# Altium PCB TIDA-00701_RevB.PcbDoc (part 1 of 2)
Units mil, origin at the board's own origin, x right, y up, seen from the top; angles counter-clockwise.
Board outline 4724.41 x 3228.35 mil, 2 copper layers (Top Layer, Bottom Layer), stack 62 mil thick; 170 components, 75 nets, 385 pads, 92 vias.
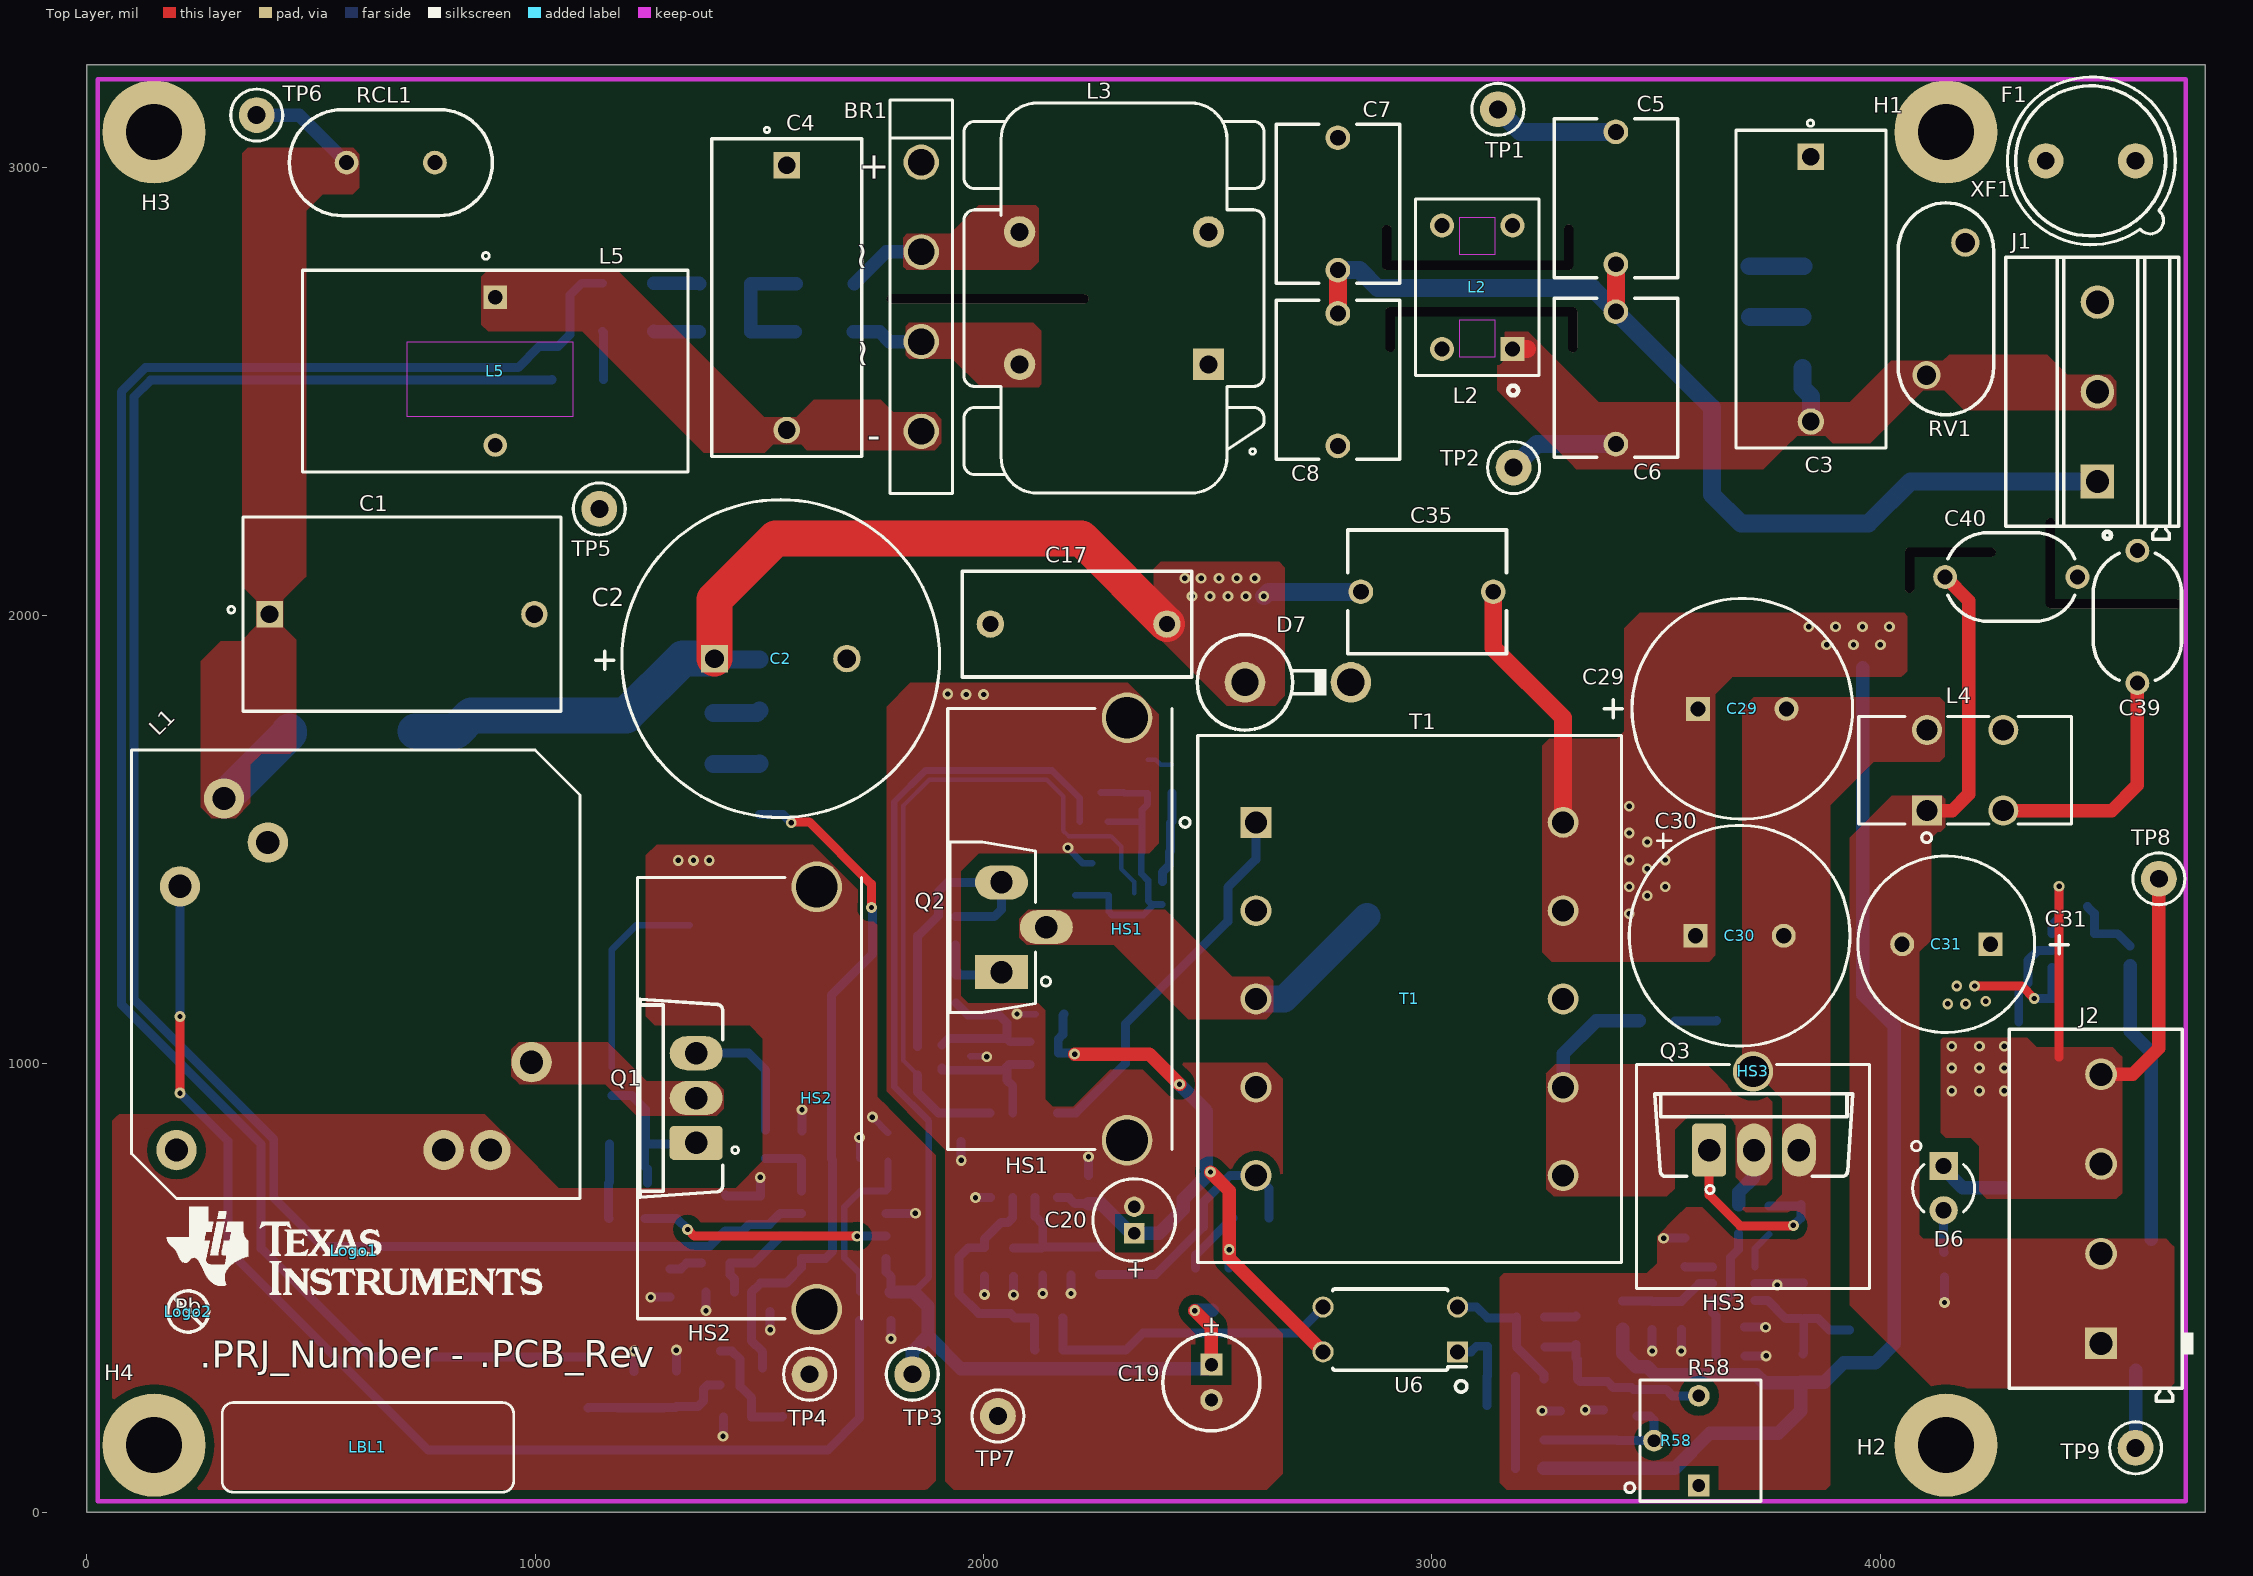
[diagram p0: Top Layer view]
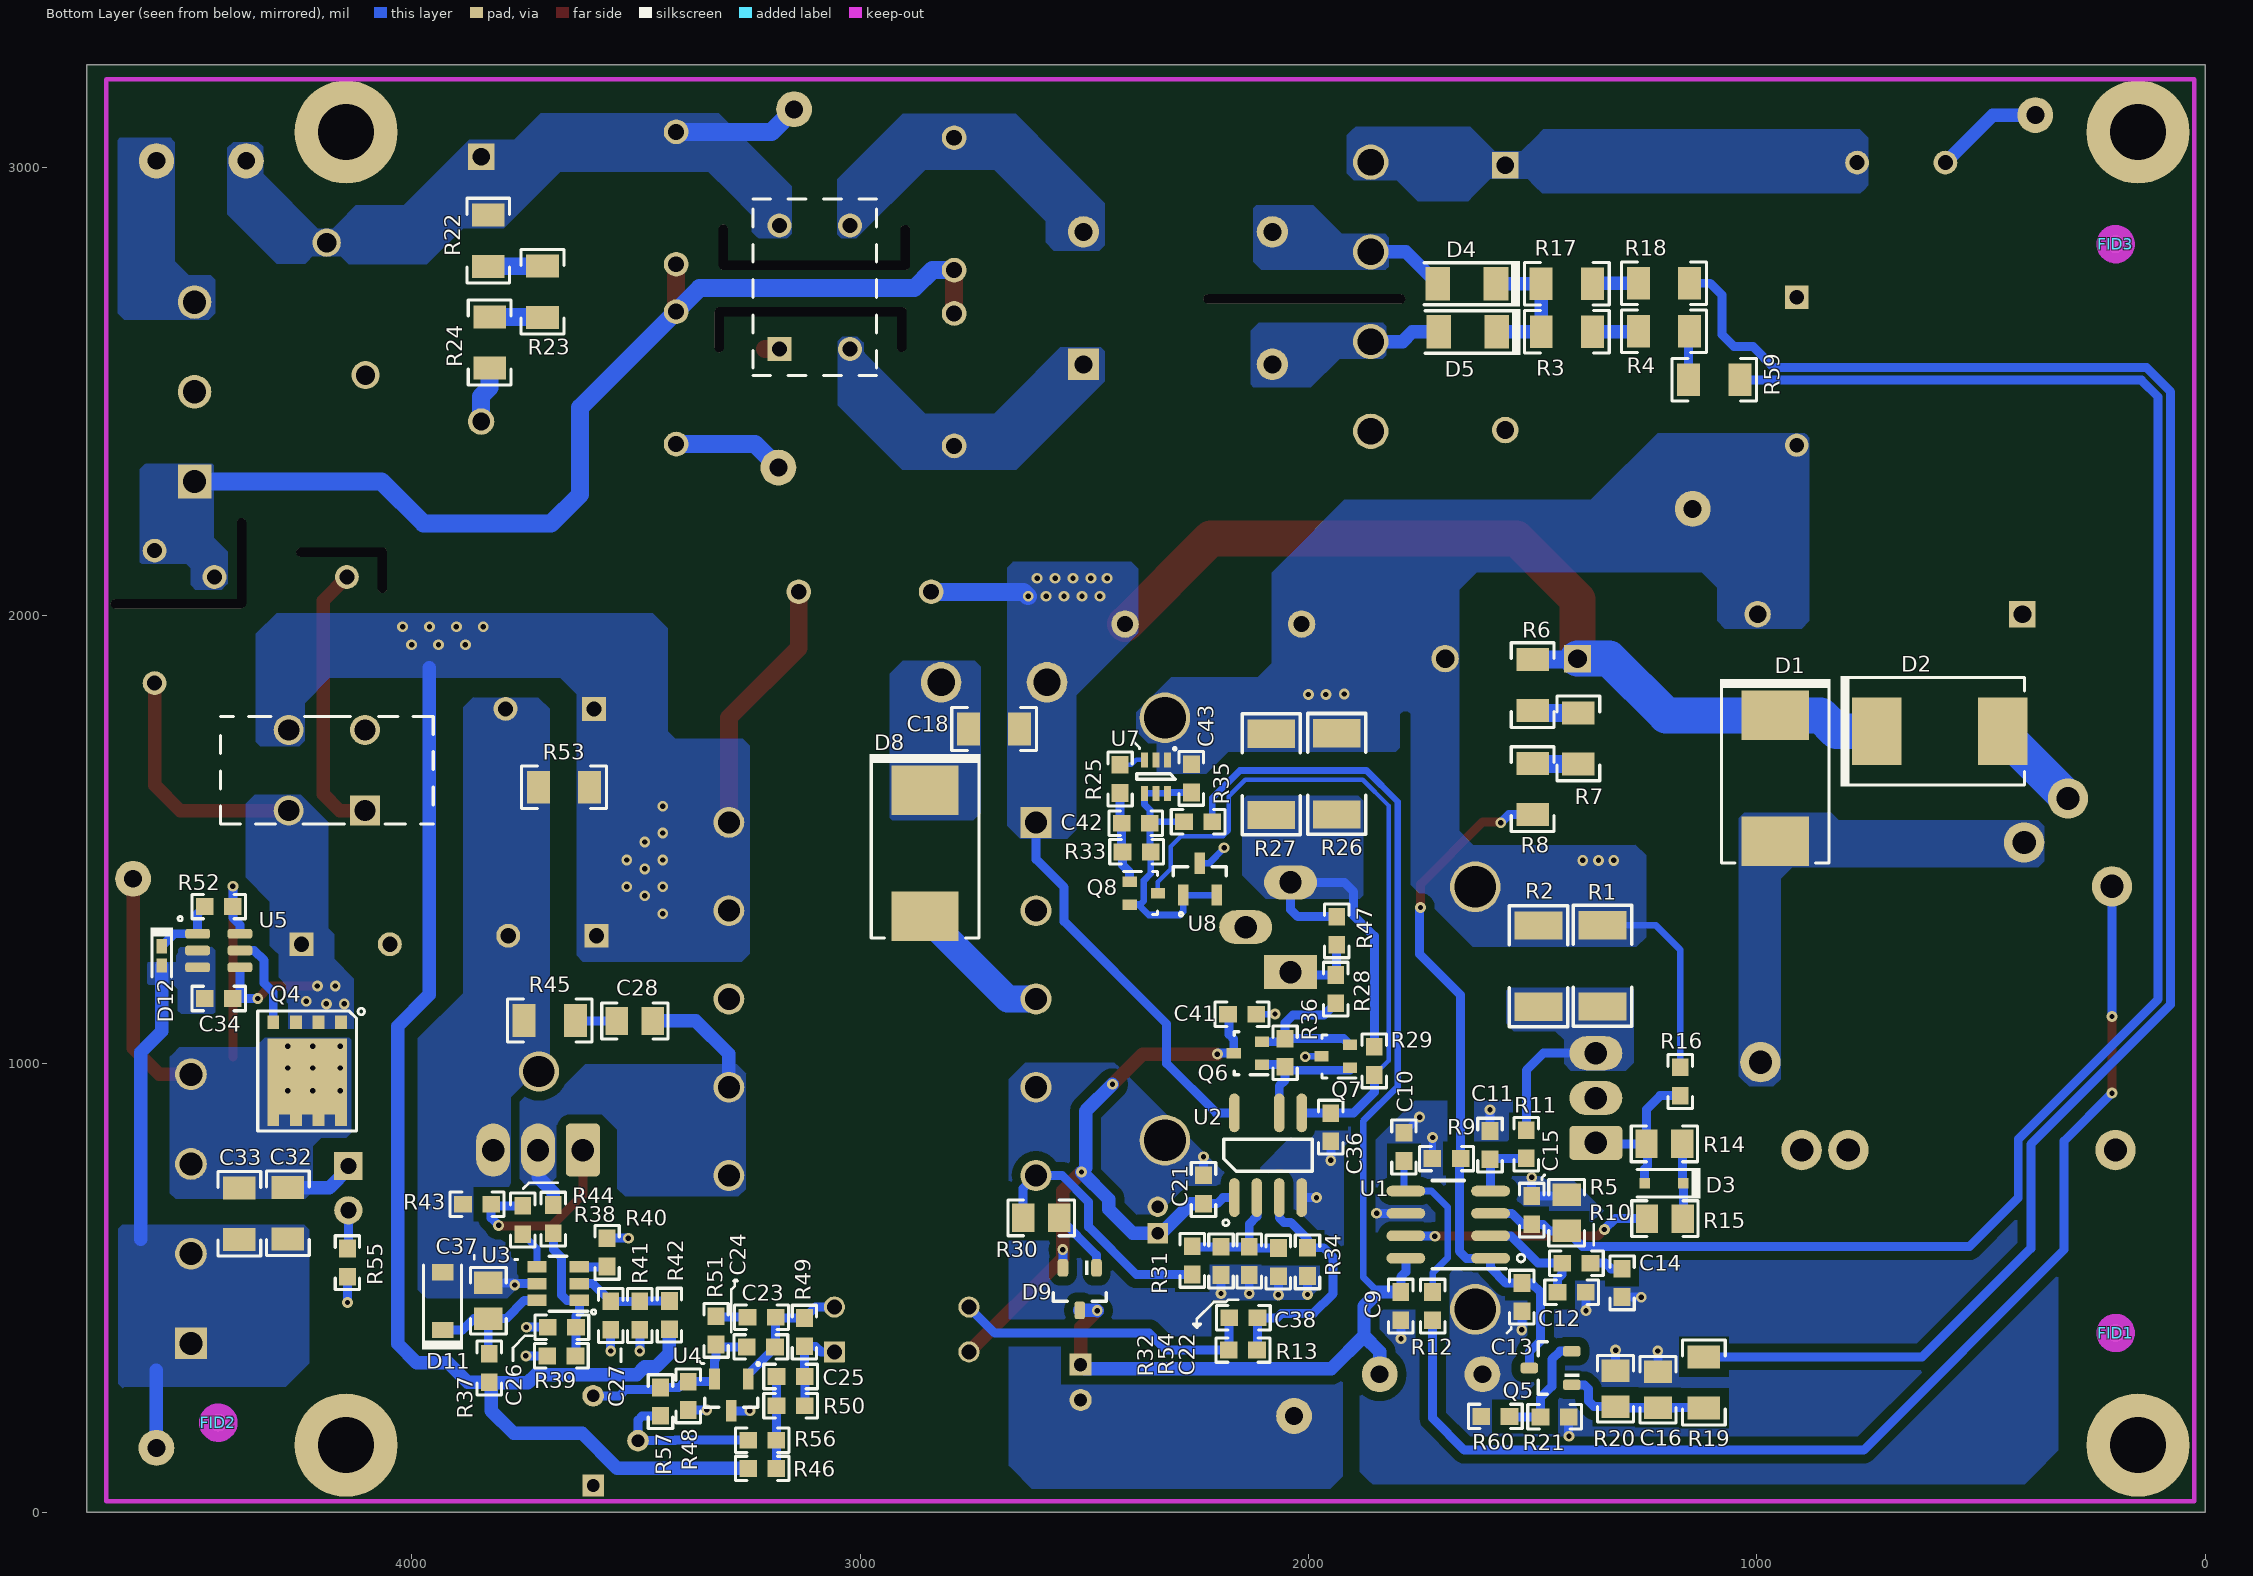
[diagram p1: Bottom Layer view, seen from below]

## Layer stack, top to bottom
Top Solder: solder mask 0.4, Solder Resist, Dk 3.5
Top Layer: signal copper 1.4
Dielectric1: core 59.2, FR-4, Dk 4.8
Bottom Layer: signal copper 1.4
Bottom Solder: solder mask 0.4, Solder Resist, Dk 3.5

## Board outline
0,0 0,3228.35 4724.41,3228.35 4724.41,0

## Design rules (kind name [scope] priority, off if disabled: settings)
AcuteAngle [All] p1: minimum=4.50000000000000E+0001 checktracksonly=FALSE
AssemblyTestPointUsage [All] p1: valid=2
Clearance Clearance_1 [IsSMTPin vs IsVia] p1: gap=8
Clearance Clearance_Poly [InPolygon] p2: gap=20
Clearance [All] p3: gap=8
ComponentClearance ComponentClearance_Shunt [InComponentClass('Header') vs InComponentClass('Shunt')] p1: gap=0 collisioncheckmode=3 verticalgap=0 showdistances=FALSE
ComponentClearance ComponentClearance_MountingHoles_FiducialMarks [InComponentClass('Mounting Holes') vs InComponentClass('FiducialMark')] p2: gap=20 collisioncheckmode=3 verticalgap=10 showdistances=FALSE
ComponentClearance ComponentClearance_Logo [InComponentClass('Logo')] p3: gap=0 collisioncheckmode=3 verticalgap=0 showdistances=FALSE
ComponentClearance ComponentClearance_ScrewToNut [(HasFootprint('NY PMS 440 0025 PH')) vs (HasFootprint('Keystone_1902C'))] p4: gap=5 collisioncheckmode=3 verticalgap=10 showdistances=FALSE
ComponentClearance ComponentClearance_MountingHoles [InComponentClass('Mounting Holes')] p5: gap=50 collisioncheckmode=3 verticalgap=100000 showdistances=FALSE
ComponentClearance ComponentClearance_SmallPassives [HasFootprint('0201*') or HasFootprint('0402*') or HasFootprint('0508') or HasFootprint('0603*') or HasFootprint('0612') or HasFootprint('0805*') or HasFootprint('0815*') or HasFootprint('0830*') or HasFootprint('1206*') or HasFootprint('1210*') or HasFootprint('1808*') or HasFootprint('1812*') or HasFootprint('1825*') or HasFootprint('2010*') or HasFootprint('2220*') or HasFootprint('2225*') or HasFootprint('2512*') or HasFootprint('2728*') or HasFootprint('3518*') vs HasFootprint('0201*') or HasFootprint('0402*') or HasFootprint('0508') or HasFootprint('0603*') or HasFootprint('0612') or HasFootprint('0805*') or HasFootprint('0815*') or HasFootprint('0830*') or HasFootprint('1206*') or HasFootprint('1210*') or HasFootprint('1808*') or HasFootprint('1812*') or HasFootprint('1825*') or HasFootprint('2010*') or HasFootprint('2220*') or HasFootprint('2225*') or HasFootprint('2512*') or HasFootprint('2728*') or HasFootprint('3518*')] p6: gap=10 collisioncheckmode=3 verticalgap=10 showdistances=FALSE
DiffPairsRouting [All] p1: maxlimit=100 minlimit=10 mostfreqgap=10 toplayer_minwidth=15 toplayer_maxwidth=15 toplayer_prefwidth=15 bottomlayer_minwidth=15 bottomlayer_maxwidth=15 bottomlayer_prefwidth=15 maxuncoupledlength=1000
FabricationTestPointUsage TestPointUsage [All] p1: valid=2 allowmultiple=FALSE
FabricationTestpoint Testpoint [All] p1: side=3 testpointundercomponent=TRUE minsize=40 maxsize=100 preferedsize=60 minholesize=0 maxholesize=40 preferedholesize=32 testpointgrid=1 allowsidetop=TRUE allowsidebottom=TRUE usegrid=TRUE gridtolerance=0.01
FanoutControl Fanout_LCC [IsLCC] p1: bgadir=Out bgaviamode=Centered fanoutstyle=Auto fanoutdirection=Alternating viagrid=1 // Fanout_LCC (Default Rule)
FanoutControl Fanout_BGA [IsBGA] p2: bgadir=Out bgaviamode=Centered fanoutstyle=Auto fanoutdirection=Alternating viagrid=1 // Fanout_BGA (Default Rule)
FanoutControl Fanout_Default [All] p4: bgadir=Out bgaviamode=Centered fanoutstyle=Auto fanoutdirection=Alternating viagrid=1 // Fanout_Default (Default Rule)
FanoutControl Fanout_Small [(CompPinCount < 5)] p5: bgadir=Out bgaviamode=Centered fanoutstyle=Auto fanoutdirection=OutThenIn viagrid=1 // Fanout_Small (Default Rule)
Height [All] p1: minheight=0 maxheight=2000 prefheight=100
HoleSize [All] p1: absolutevalues=TRUE maxlimit=251 minlimit=8 maxpercent=80.000 minpercent=20.000
MinimumAnnularRing MinimumAnnularRing_ThermalPadVias [IsVia and InAnyComponent] p1: minimumring=5.91
MinimumAnnularRing [All] p2: minimumring=9
MinimumSolderMaskSliver MinimumSolderMaskSliver_Logo [InComponentClass('Logo') vs InComponentClass('Logo')] p1: minsoldermaskwidth=0.7
MinimumSolderMaskSliver [All] p2: minsoldermaskwidth=3.94
PlaneConnect [All] p1: planeconnectstyle=Direct reliefexpansion=10 reliefentries=4 reliefconductorwidth=10 reliefairgap=10
PolygonConnect [All] p1: connectstyle=Direct reliefconductorwidth=10 reliefentries=4 polygonreliefangle="90 Angle" airgapwidth=10
RoutingVias ThermalPadVias [IsVia and InAnyComponent] p1: holewidth=7.87 width=19.68 viastyle="Through Hole" minholewidth=7.87 minwidth=19.68 maxholewidth=12.99 maxwidth=23.62
RoutingVias [All] p2: holewidth=12 width=24 viastyle="Through Hole" minholewidth=7.87 minwidth=24 maxholewidth=16 maxwidth=34
SilkToSilkClearance SilkToSilkClearance_Pb-FreeLogo [(HasFootprint('Pb-Free_Overlay_Medium') OR HasFootprint('Pb-Free_Overlay_Small')) vs (HasFootprint('Pb-Free_Overlay_Medium') OR HasFootprint('Pb-Free_Overlay_Small'))] p1: silktosilkclearance=0
SilkToSilkClearance [All] p2: silktosilkclearance=5
SilkToSolderMaskClearance SilkscreenOverComponentPads [IsPad] p1: minsilkscreentomaskgap=1 clearancetoexposedcopper=TRUE
SolderMaskExpansion [All] p1: expansion=2.5
UnpouredPolygon [All] p1: allowunpoured=FALSE
Width [All] p1: maxlimit=120 minlimit=6 preferedwidth=10 checkconnectedcopper=TRUE
14 further rules are at their usual default settings.

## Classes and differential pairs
net class HV_net: NetR6_2 NetR17_1
component class TIDA-00701_PFC: BR1 C1 C2 C3 C4 C5 C6 C7 C8 C9 C10 C11 C12 C13 C14 C15 C16 C42 C43 D1 D2 D3 D4 D5 F1 HS1 J1 L1 L2 L3 L5 Q1 Q5 Q8 R1 R2 R3 R4 R5 R6 R7 R8 R9 R10 R11 R12 R14 R15 R16 R17 R18 R19 R20 R21 R22 R23 R24 R25 R33 R35 R59 R60 RCL1 RV1 TP1 TP2 TP3 TP4 TP5 TP6 U1 U7 U8 XF1
component class TIDA-00701_Flyback: C17 C18 C19 C20 C21 C22 C23 C24 C25 C26 C27 C28 C29 C30 C31 C32 C33 C34 C35 C36 C37 C38 C39 C40 C41 D6 D7 D8 D9 D11 D12 HS2 HS3 J2 L4 Q2 Q3 Q4 Q6 Q7 R13 R26 R27 R28 R29 R30 R31 R32 R34 R36 R37 R38 R39 R40 R41 R42 R43 R44 R45 R46 R47 R48 R49 R50 R51 R52 R53 R54 R55 R56 R57 R58 T1 TP7 TP8 TP9 U2 U3 U4 U5 U6
component class Hardware_ANSI-B: !PCB1 FID1 FID2 FID3 H1 H2 H3 H4 LBL1 Logo1 Logo2 Logo3 ZZ1 ZZ2 ZZ3 ZZ4

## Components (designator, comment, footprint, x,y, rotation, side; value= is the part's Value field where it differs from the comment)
BR1 "GBU6J" GBU 1861,2711 r270 top
C1 "B32922C3684M" B32922_18.5mm 703,2003 r0 top
C2 "UCY2W820MHD6" CAPPRD750W80D1800H3150 1547.64,1904.05 r0 top
C3 "B32922C3334M" B32922_14.5mm 3845,2728 r270 top
C4 "B32922C3334M" B32922_14.5mm 1561,2709 r270 top
C5 "CS75ZU2GA152MYNKA" E_900x700x900 3410,2931 r270 top
C6 "CS75ZU2GA152MYNKA" E_900x700x900 3410,2530 r90 top
C7 "CS80ZU2GA222MYNKA" E_900x700x900 2790,2918 r270 top (schematic designator C43)
C8 "CS80ZU2GA222MYNKA" E_900x700x900 2790,2526 r90 top (schematic designator C39)
C9 "GRM188R61H105KAALD" 0603 1794,460 r270 bottom
C10 "GRM1885C1H180JA01D" 0603 1787,815 r90 bottom
C11 "C1608C0G1H102J" 0603 1595,819 r90 bottom
C12 "C1608X5R1C105K" 0603 1412.96,491.13 r180 bottom
C13 "C1608C0G1H102J" 0603 1524,480 r270 bottom
C14 "C1608X5R1E335K080AC" 0603 1300.5,511.76 r270 bottom
C15 "C1608C0G1H102J" 0603 1502,674 r90 bottom
C16 "C2012X5R1E106K125AB" 0805_HV 1220.22,273.72 r90 bottom
C17 "B32921C3104M" B32921_1300x1200x600 2212,1981 r180 top
C18 "C3216X7R2J222K" 1206 2701,1747 r0 bottom
C19 "35ZLJ47MTA5X11" ZLJ_500x1100 2508,290 r270 top
C20 "UVR1H100MDD6TP" FC_400x1100 2336,652 r90 top
C21 "C1608X7R1H104K" 0603 2234,720 r90 bottom
C22 "06035A4R7CAT2A" 0603 2067,558 r270 bottom
C23 "C1608C0G1H102J" 0603 3219.5,435.42 r0 bottom
C24 "C0603C681K5RACTU" 0603 3221,369 r0 bottom
C25 "06035A100JAT2A" 0603 3154.58,303 r180 bottom
C26 "06035A2R2CAT2A" 0603 3665,413 r0 bottom
C27 "06035A470JAT2A" 0603 3556,439 r90 bottom
C28 "C2012X7R2E103K" 0805_HV 3502,1096 r180 bottom
C29 "EKY-350ELL122MK30S" CAPPRD500W60D1250H3000 3692,1792 r0 top
C30 "EKY-350ELL122MK30S" CAPPRD500W60D1250H3000 3686,1286 r0 top
C31 "680uF" CAPPRD500W60D1000H3000 4147,1267 r180 top
C32 "C3216X7R1H105K" 1206 4276,667 r270 bottom
C33 "C1206C104J5RACTU" 1206 4384,666 r270 bottom
C34 "GRM188R61H105KAALD" 0603 4430,1146 r0 bottom
C35 "CS80ZU2GA222MYNKA" E_900x700x900 2989,2053 r0 top
C36 "06035A5R6CAT2A" 0603 1950,859 r270 bottom
C37 "GRM21BR71H474KA88L" 0805_HV 3829,472 r270 bottom
C38 "C1608X7R1H473K" 0603 2145,434.03 r0 bottom
C39 "VY2472M49Y5US63V7" CAPRD750W60D750H1050 4573,1997 r90 top (schematic designator C7)
C40 "VY2472M49Y5US63V7" CAPRD750W60D750H1050 4292,2086 r0 top (schematic designator C8)
C41 "C1608X7R1H104K" 0603 2148,1111 r180 bottom
C42 "GRM188R61C104KA01D" 0603 2385,1537 r180 bottom
C43 "C1608X7R1C224K" 0603 2261,1637 r90 bottom (schematic designator C40)
D1 "MURS360T3G" SMC 959,1637 r270 bottom
D2 "RS3J-13-F" SMC 592,1742 r180 bottom
D3 "MMDL914-TP" sod-323 1207,734 r0 bottom
D4 "CGRM4007-G" MINI-SMA 1646.71,2740.06 r0 bottom
D5 "CGRM4007-G" MINI-SMA 1644.71,2632.65 r0 bottom
D6 "HLMP1503" LED_HLMP1523 4141,723 r270 top
D7 "1.5KE130A" DO-201AD_Vert 2701,1851 r180 top
D8 "STTH310S" SMC 2855,1470 r270 bottom
D9 "BAV23S-7-F" SOT-23 2510,498 r270 bottom
D11 "MMSZ5252B-7-F" SOD-123 3931,471 r90 bottom
D12 "BZT52C4V7T-7" SOD-523 4557,1241 r270 bottom
F1 "37212000001" FUSE_372 4469,3014 r0 top
FID1 "Fiducial" Fiducial10-20 200,400 r180 bottom
FID2 "Fiducial" Fiducial10-20 4431,200 r180 bottom
FID3 "Fiducial" Fiducial10-20 200,2828.35 r180 bottom
H1 "PMSSS 440 0025 PH" B_F_PMSSS4400025PH 4146,3078.35 r0 top
H2 "PMSSS 440 0025 PH" B_F_PMSSS4400025PH 4146,150 r0 top (schematic designator H1)
H3 "PMSSS 440 0025 PH" B_F_PMSSS4400025PH 150,3078.35 r0 top (schematic designator H1)
H4 "PMSSS 440 0025 PH" B_F_PMSSS4400025PH 150,150 r0 top (schematic designator H1)
HS1 "593002B00000G" HEATSINK_593002B03400G 2170,1301 r90 top
HS2 "593002B00000G" HEATSINK_593002B03400G 1478,924 r90 top
HS3 "V7237C" HEATSINK_V7237C 3716,749 r0 top
J1 "1715734" Phoenix_1715734 4484,2499 r90 top
J2 "1715747" Phoenix_1715747 4492,677 r90 top
L1 "750343062" XFMR_CTX16-17298 600,1200 r315 top
L2 "750311982" 750311982 3101,2732 r90 top
L3 "744823220" IND_WE-CMB_M 2291,2708 r180 top
L4 "750311982" IND_750343094 4189,1655 r0 top
L5 "2116-V-RC" IND_2118-V-RC 911,2545 r270 top
LBL1 "Size: 0.65\" x 0.20 \"" Label_650x200 627,145 r0 top
Logo1 "Texas Instruments" TI_STACKED_OVERLAY_SMALL 597,583 r0 top
Logo2 "Pb-Free Symbol" Pb-Free_Overlay_Small 226,448 r0 top
Logo3 "FCC disclaimer" FCC_disclaimer 2290,3340 r0 top
Q1 "IPA60R330P" TO-220AB 1359,924 r90 top
Q2 "AOTF15S65L" TO-220_FullPAK_Offset 2040,1305 r90 top
Q3 "IRFI4227PBF" TO-220AB 3718,808 r0 top
Q4 "CSD18504Q5A" TRANS_NexFET_Q5A 4233,984 r270 bottom
Q5 "MMBT2222A" SOT-23 1460,322 r0 bottom
Q6 "MMBT4401WT1G" SOT-323 2135,1024 r0 bottom
Q7 "MMBT4403WT1G" SOT-323 1939,1017 r0 bottom
Q8 "MMBT4403WT1G" SOT-323 2367,1381 r180 bottom
R1 "CSRN2010FKR300" 2010 1344,1219 r270 bottom
R2 "CRCW20102R70JNEF" 2010 1487,1218 r270 bottom
R3 "RC1206FR-07680KL" 1206 1423.71,2633.06 r180 bottom
R4 "RC1206FR-07680KL" 1206 1207,2634 r180 bottom
R5 "CRCW08058K25FKEA" 0805_HV 1424,668 r270 bottom
R6 "CRCW1206340KFKEA" 1206 1500,1845 r270 bottom
R7 "CRCW1206340KFKEA" 1206 1398,1726 r90 bottom
R8 "CRCW1206340KFKEA" 1206 1500,1613 r90 bottom
R9 "CRCW060310K5FKEA" 0603 1692,789 r180 bottom
R10 "CRCW06035K11FKEA" 0603 1402.5,555.76 r0 bottom
R11 "CRCW0603332RFKEA" 0603 1514,821 r90 bottom
R12 "CRCW060322K1FKEA" 0603 1723,460 r270 bottom
R13 "CRCW0603100KFKEA" 0603 2146,362.03 r180 bottom
R14 "CRCW080510R0FKEA" 0805_HV 1206,822 r0 bottom
R15 "CRCW08051R10JNEA" 0805_HV 1205,655 r180 bottom
R16 "CRCW060310K0FKEA" 0603 1171,961 r90 bottom
R17 "CRCW1206301KFKEA" 1206 1423.76,2740.1 r0 bottom
R18 "CRCW1206301KFKEA" 1206 1207.06,2741.04 r180 bottom
R19 "RC1206FR-075K1L" 1206 1118.22,289.72 r90 bottom
R20 "CRCW08056K81FKEA" 0805_HV 1315.22,275.72 r90 bottom
R21 "RC0603FR-0714K7L" 0603 1451,213 r180 bottom
R22 "CRCW1206221KFKEA" 1206 3829,2836 r270 bottom
R23 "CRCW1206221KFKEA" 1206 3708,2722 r270 bottom
R24 "CRCW1206221KFKEA" 1206 3826,2609 r270 bottom
R25 "CRCW060310K0FKEA" 0603 2420,1635.65 r270 bottom
R26 "RMCF2010FT1R47" 2010 1937,1647 r270 bottom
R27 "MCR50JZHFLR180" 2010 2083,1646 r270 bottom
R28 "CRCW06035R10JNEA" 0603 1939,1167 r90 bottom
R29 "CRCW06031K21FKEA" 0603 1853,1007 r90 bottom
R30 "CRCW080547R5FKEA" 0805_HV 2596,657 r0 bottom
R31 "CRCW060371K5FKEA" 0603 2259,562 r270 bottom
R32 "CRCW060319K6FKEA" 0603 2194.94,560.78 r90 bottom
R33 "CRCW0603100KFKEA" 0603 2383,1473 r180 bottom
R34 "CRCW060320K5FKEA" 0603 2002,558.65 r90 bottom
R35 "CRCW060313K7FKEA" 0603 2246,1540 r0 bottom
R36 "CRCW06030000Z0EA" 0603 2052,1025 r90 bottom
R37 "CRCW0603402RFKEA" 0603 3827,322 r90 bottom
R38 "CRCW0603750KFKEA" 0603 3684,654 r90 bottom
R39 "CRCW060310K0FKEA" 0603 3666,349 r180 bottom
R40 "CRCW060310K0FKEA" 0603 3564,580 r90 bottom
R41 "CRCW060347K5FKEA" 0603 3491,439 r270 bottom
R42 "CRCW0603750KFKEA" 0603 3425,440 r90 bottom
R43 "CRCW060320K0FKEA" 0603 3854,687 r0 bottom
R44 "CRCW06031R50FKEA" 0603 3752,652 r90 bottom
R45 "CRCW1206100RFKEA" 1206 3692,1097 r0 bottom
R46 "CRCW060347R5FKEA" 0603 3218,98 r180 bottom
R47 "CRCW0603100KFKEA" 0603 1937,1297 r270 bottom
R48 "CRCW060344K2FKEA" 0603 3383,260 r270 bottom
R49 "CRCW06031K00FKEA" 0603 3124,402 r270 bottom
R50 "CRCW06031K50FKEA" 0603 3154.58,238 r180 bottom
R51 "CRCW06034K99FKEA" 0603 3321,406 r90 bottom
R52 "CRCW060310K0FKEA" 0603 4430,1351 r0 bottom
R53 "CRCW1206100KFKEA" 1206 3660,1617 r180 bottom
R54 "RC0603FR-07470KL" 0603 2131.94,560.78 r90 bottom
R55 "CRCW06031K21FKEA" 0603 4143,557 r90 bottom
R56 "CRCW0603332KFKEA" 0603 3218,161 r180 bottom
R57 "CRCW0603100KFKEA" 0603 3445,247 r270 bottom
R58 "25PR100KLF" POT_25PXXXXXX 3599,160 r90 top
R59 "RC1206FR-07680KL" 1206 1095,2526 r180 bottom
R60 "RT0603BRD07493KL" 0603 1583,214 r180 bottom
RCL1 "B57236S479M" THERM_B57236S0 678,3010 r0 top
RV1 "S10K275E2" VAR_S10K275E2 4146,2684 r90 top
T1 "750343004" WE_75034300X 2950,1145 r270 top
TP1 "5000" Keystone5000 3147,3129 r0 top
TP2 "5000" Keystone5000 3182,2330 r0 top
TP3 "5000" Keystone5000 1841,308 r0 top
TP4 "5001" Keystone5001 1612,308 r0 top
TP5 "5001" Keystone5001 1143,2238 r0 top
TP6 "5001" Keystone5001 379,3116 r90 top
TP7 "5001" Keystone5001 2032,215 r0 top
TP8 "5000" Keystone5000 4621,1413 r0 top
TP9 "5001" Keystone5001 4569,144 r0 top
U1 "UCC28051D" D0008A_N 1688.22,641.72 r0 bottom
U2 "UCC28740DR" D0007A_N 2090.07,796.51 r90 bottom
U3 "UCC24636DBV" DBV0006A_N 3673,510 r0 bottom
U4 "TL431BQDBZ" DBZ0003A_L 3287,262 r270 bottom
U5 "LM5050-2" tsop-6 4430,1253 r180 bottom
U6 "LTV-817" DIP762W60P254L460H350Q4B 2907,408 r180 top
U7 "TMP302CIDCK" DCK0006A_N 2340,1641 r270 bottom
U8 "TL431BQDBZ" DBZ0003A_L 2242,1412 r90 bottom
XF1 "56000001009" FuseHolder_560000010 4469,3014 r0 top
ZZ1 "This Assembly Note is for PCB labels only" AssemblyNoteLabel 196,3593 r0 top
ZZ2 "These assemblies are ESD sensitive, ESD precautions shall be observed." AssemblyNote 197,3513 r0 top
ZZ3 "These assemblies must be clean and free from flux and all contaminants. Use of no clean flux is not acceptable." AssemblyNote 197,3424.44 r0 top
ZZ4 "These assemblies must comply with workmanship standards IPC-A-610 Class 2, unless otherwise specified." AssemblyNote 197,3335.89 r0 top

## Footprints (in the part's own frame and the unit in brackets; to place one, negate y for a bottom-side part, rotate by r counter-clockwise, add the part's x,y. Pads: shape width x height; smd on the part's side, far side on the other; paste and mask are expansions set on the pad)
0603 [mm] "0603 from SM-752 data"
  rect 1x0.95 smd: 1(-0.8,0) 2(0.8,0)
  silkscreen extent -1.52,-0.69 1.52,0.69, body extent -0.87,-0.47 0.87,0.47, height 0.85
0805_HV [mil] "0805 with 30mil clearance between pads"
  rect 50x63 smd: 1(-40,0) 2(40,0)
  silkscreen extent -74,-40 74,40, body extent -43,-29 43,29, height 43
1206 [mm] "1206 from SM-752 data"
  rect 1.3x1.85 smd: 1(-1.45,0) 2(1.45,0)
  silkscreen extent -2.4,-1.21 2.4,1.21, body extent -1.7,-0.9 1.7,0.9, height 1.35
2010 [mm] "Chip Capacitor, Body 5.08x2.54mm, IPC Medium Density"
  rect 1.6x2.7 smd: 1(-2.3,0) 2(2.3,0)
  silkscreen extent -3.42,-1.65 3.42,1.65, body extent -2.73,-1.45 2.73,1.45, height 1.66
750311982 [mm] "4 LEAD,TH"
  rect 1.362x1.362 / inner round 1.362 / far side rect 1.362x1.362 hole 0.854: 1(-3.5,-2)
  round 1.362 hole 0.854: 2(-3.5,2) 3(3.5,2) 4(3.5,-2)
  Top Layer keep-out region: 1.873,-1.027 3.928,-1.027 3.928,1.027 1.873,1.027
  Top Layer keep-out region: -3.926,-1.027 -1.872,-1.027 -1.872,1.027 -3.926,1.027
  silkscreen extent -6.12,-3.5 5,3.5, body extent -5,-3.5 5,3.5, height 6.8
AssemblyNote [mil] "Assembly Note"
AssemblyNoteLabel [mil] "Assembly Note for PCB Labels"
B32921_1300x1200x600 [mm] "EPCOS"
  round 1.55 hole 0.9: 1(-5,0) 2(5,0)
  silkscreen extent -6.4,-3 6.6,3, body extent -6.4,-3 6.6,3, height 12
B32922_14.5mm [mm] "Epcos film capacitors, 15mm spacing"
  rect 1.5x1.5 hole 1: 1(-7.5,0)
  round 1.5 hole 1: 2(7.5,0)
  silkscreen extent -9,-4.25 9,4.25, body extent -9,-4.25 9,4.25, height 14.5
B32922_18.5mm [mm] "Epcos film capacitors, 15mm spacing"
  rect 1.5x1.5 hole 1: 1(-7.5,0)
  round 1.5 hole 1: 2(7.5,0)
  silkscreen extent -9,-5.5 9,5.5, body extent -9,-5.5 9,5.5, height 18.5
B_F_PMSSS4400025PH [mil] "MACHINE SCREW PAN PHILLIPS 4-40"
  round 230 hole 125: 1(0,0)
  body extent -109,-109 110,110, height 79
CAPPRD500W60D1000H3000 [mil] "CAPACITOR, POLARIZED, 0.6MM LEAD DIA, PITCH 5MM"
  rect 53.31x53.31 / inner round 53.31 / far side rect 53.31x53.31 hole 33.62: 1(-98.43,0)
  round 53.31 hole 33.62: 2(98.43,0)
  silkscreen extent -272,-197 197,197, body extent -195,-196 197,196, height 1240
CAPPRD500W60D1250H3000 [mm] "CAPACITOR, POLARIZED, 0.6MM LEAD DIA, PITCH 5MM"
  rect 1.354x1.354 / inner round 1.354 / far side rect 1.354x1.354 hole 0.854: 1(-2.5,0)
  round 1.354 hole 0.854: 2(2.5,0)
  silkscreen extent -7.82,-6.25 6.25,6.25, body extent -6.2,-6.24 6.25,6.24, height 31.5
CAPPRD750W80D1800H3150 [mm] "CAPACITOR, POLARIZED, 0.8MM LEAD DIA, PITCH 7.5MM"
  rect 1.554x1.554 / inner round 1.554 / far side rect 1.554x1.554 hole 1.054: 1(-3.75,0)
  round 1.554 hole 1.054: 2(3.75,0)
  silkscreen extent -10.46,-9 9,9, body extent -8.93,-8.98 9,8.98, height 33
CAPRD750W60D750H1050 [mm] "Vishay BC Components"
  round 1.35 hole 0.85: 1(-3.75,0) 2(3.75,0)
  silkscreen extent -3.6,-2.51 3.6,2.51, body extent -4.05,-2.5 4.05,2.5, height 10.49
D0007A_N [mm] "SOIC, 7-Leads, Body 4.9x3.9mm, Pitch 1.27mm, IPC Medium Density"
  oval 2.2x0.6 smd: 1(-2.4,1.905) 2(-2.4,0.635) 3(-2.4,-0.635) 4(-2.4,-1.905) 5(2.4,-1.905) 6(2.4,-0.635) 8(2.4,1.905)
  silkscreen extent -0.9,-2.5 0.9,2.5, body extent -3,-2.5 3,2.5, height 1.54
D0008A_N [mm] "SOIC, 8-Leads, Body 4.9x3.9mm, Pitch 1.27mm, IPC Medium Density"
  oval 2.2x0.6 smd: 1(-2.4,1.905) 2(-2.4,0.635) 3(-2.4,-0.635) 4(-2.4,-1.905) 5(2.4,-1.905) 6(2.4,-0.635) 7(2.4,0.635) 8(2.4,1.905)
  silkscreen extent -3.3,-2.5 0.9,2.5, body extent -3,-2.45 3,2.45, height 1.63
DBV0006A_N [mm] "SOT23, 6-Leads, Body 2.9x1.6mm, Pitch 0.95mm, Lead Span 2.8mm, IPC Medium Density"
  rect 1.1x0.65 smd: 1(-1.2,0.95) 2(-1.2,0) 3(-1.2,-0.95) 4(1.2,-0.95) 5(1.2,0) 6(1.2,0.95)
  silkscreen extent -1.67,-1.55 0.5,1.55, body extent -1.42,-1.46 1.42,1.46, height 1.11
DBZ0003A_L [mm] "SOT23, 3-Leads, Body 2.9x1.3mm, Pitch 0.95mm, Lead Span 2.4mm, IPC High Density"
  rect 1.2x0.6 smd: 1(-0.9,0.95) 2(-0.9,-0.95) 3(0.9,0)
  silkscreen extent 0.2,-1.5 0.7,1.5, body extent -1.26,-1.46 1.26,1.46, height 0.96
DCK0006A_N [mm] "SOT23, 6-Leads, Body 2x1.3mm, Pitch 0.65mm, Lead Span 2.1mm, IPC Medium Density"
  rect 0.85x0.4 smd: 1(-0.95,0.65) 2(-0.95,0) 3(-0.95,-0.65) 4(0.95,-0.65) 5(0.95,0) 6(0.95,0.65)
  silkscreen extent -0.15,-1.1 0.15,1.1, body extent -1.14,-1 1.14,1, height 0.94
DIP762W60P254L460H350Q4B [mm] "LITE-ON"
  rrect8% 1.2x1.2 hole 0.85: 1(-3.81,1.27)
  round 1.2 hole 0.85: 2(-3.81,-1.27) 3(3.81,-1.27) 4(3.81,1.27)
  silkscreen extent -4.34,-2.29 3.25,3.55, body extent -3.94,-2.3 3.94,2.3, height 4.3
DO-201AD_Vert [mm] "DO-201AD VERTICAL FOOTPRINT"
  round 2.3 hole 1.55: 1(-3,0) 2(3,0)
  silkscreen extent -1.62,-2.7 5.7,2.7, body extent -3.66,-2.66 5.66,2.65, height 14.8
E_900x700x900 [mm] "TH, 2- Leads, Body 9x7mm, Pin Spacing 7.5mm"
  round 1.4 hole 0.9: 1(-3.75,0) 2(3.75,0)
  silkscreen extent -4.5,-3.5 4.5,3.5, body extent -4.49,-3.5 4.49,3.5, height 11.96
FC_400x1100 [mm] "Panasonic"
  rect 1.15x1.15 hole 0.7: 1(-0.75,0)
  round 1.15 hole 0.7: 2(0.75,0)
  silkscreen extent -2.33,-2.33 2.33,2.33, body extent -2.23,-2.25 2.25,2.25, height 12.01
FCC_disclaimer [mil]
Fiducial10-20 [mm]
  round 1 smd mask+0.5: 1(0,0)
  Top Layer keep-out circle w1.178: c0,0 r0.5
FUSE_372 [mm] "LITTELFUSE"
  round 1.5 hole 1: 1(-2.54,0) 2(2.54,0)
  silkscreen extent -4.25,-4.25 4.25,4.25, body extent -4.26,-4.26 4.26,4.26, height 8
FuseHolder_560000010 [mm] "Littelfuse fuse holder TR5"
  round 2 hole 1: 1(-2.54,0) 2(2.54,0)
  silkscreen extent -4.71,-4.75 4.79,4.75, body extent -4.75,-4.74 4.75,4.75, height 5.6
GBU [mm] "Comchip / Diodes Inc diode bridge"
  round 2 hole 1.5: 1(-7.62,0) 2(-2.54,0) 3(2.54,0) 4(7.62,0)
  silkscreen extent -11.15,-1.78 11.15,1.78, body extent -11.15,-1.76 11.15,1.8, height 21.55
HEATSINK_593002B03400G [mm] "HEATSINK, 25X12.7X29.97 MM"
  round 2.868 hole 2.36: 1(-11.965,-3.81) 1(11.965,-3.81)
  silkscreen extent -12.5,-6.35 12.5,6.35, body extent -12.5,-6.35 12.5,6.35, height 29.97
HEATSINK_V7237C [mm] "HEATSINK,TO-220,13.21X12.7MM"
  round 2.28 hole 1.78: 1(0,5.95)
  silkscreen extent -6.61,-6.35 6.61,6.35, body extent -6.61,-6.35 6.61,6.35, height 19.05
IND_2118-V-RC [mil] "INDUCTOR,2 LEAD,VERTICAL MOUNT,8.382mm PITCH,TH"
  rect 52x52 / inner round 52 / far side rect 52x52 hole 32: 1(-165,0)
  round 52 hole 32.01: 2(165,0)
  Top Layer keep-out region: -64,-196.87 100,-196.87 100,173.99 -64,173.99
  silkscreen extent -225,-430 225,430, body extent -225,-430 225,430, height 860
IND_750343094 [mm] "INDUCTOR, TH-4P"
  rect 1.7x1.7 / inner round 1.7 / far side rect 1.7x1.7 hole 1.2: 1(-2.16,-2.285)
  round 1.7 hole 1.2: 2(2.16,-2.285) 3(-2.16,2.285) 4(2.16,2.285)
  silkscreen extent -6.03,-4.1 6.03,3.05, body extent -6.03,-3.05 6.03,3.05, height 13.06
IND_WE-CMB_M [mil] "Wurth"
  rect 70x70 hole 40: 1(-210.63,147.64)
  round 70 hole 40: 2(210.63,147.64) 3(210.63,-147.64) 4(-210.63,-147.64)
  silkscreen extent -335,-435 335,435, body extent -335,-394 335,394, height 1044
Keystone5000 [mil] "For Keystone 500x miniature loop terminals"
  round 80 hole 40: 1(0,0)
  silkscreen extent -58,-58 58,58, body extent -49,-49 49,49, height 182
Keystone5001 [mil] "For Keystone 500x miniature loop terminals"
  round 80 hole 40: 1(0,0)
  silkscreen extent -58,-58 58,58, body extent -49,-49 49,49, height 182
Label_650x200 [mil] "Thermal Transfer Label"
  silkscreen extent -325,-100 325,100, body extent -326,-101 326,101, height 1
LED_HLMP1523 [mm] "Everlight Electronics"
  rect 1.6x1.6 hole 0.914: 1(-1.25,0)
  round 1.6 hole 0.914: 2(1.25,0)
  silkscreen extent -1.34,-1.75 1.34,1.75, body extent -1.6,-1.67 1.68,1.67, height 6.2
MINI-SMA [mm] "COMCHIP"
  rect 1.4x1.9 smd: 1(-1.65,0) 2(1.65,0)
  silkscreen extent -3,-1.3 2.4,1.3, body extent -1.95,-0.9 1.95,0.9, height 1.7
Pb-Free_Overlay_Small [mil]
  silkscreen extent -46,-46 46,46
Phoenix_1715734 [mm] "Phoenix"
  rect 1.9x1.9 hole 1.321: 1(-5.08,0)
  round 1.9 hole 1.321: 2(0,0) 3(5.08,0)
  silkscreen extent -8.36,-4.6 14.99,75.51, body extent -8.36,-4.6 7.62,5.2, height 14.2
Phoenix_1715747 [mm] "Terminal Block, 5.08mm, 4x1, TH"
  rect 1.8x1.8 hole 1.3: 1(-7.62,0)
  round 1.8 hole 1.3: 2(-2.54,0) 3(2.54,0) 4(7.62,0)
  silkscreen extent -10.9,-5.25 10.16,5.2, body extent -10.9,-4.6 10.16,5.2, height 14.2
POT_25PXXXXXX [mm] "Potentiometer, 25p series, through hole, 3 pin"
  rect 1.222x1.222 hole 0.714: 1(-2.54,0.1)
  round 1.222 hole 0.714: 2(0,2.64) 3(2.54,0.1)
  silkscreen extent -3.43,-3.43 3.43,4.29, body extent -3.43,-3.43 3.43,3.43, height 5.13
SMC [mil] "Molded Diode, 2-Leads, Body 6.9x5.8mm, IPC Medium Density, based on OnSemi component dimensions and land patterns"
  rect 110x150 smd: 1(-140.49,0) 2(140.49,0)
  silkscreen extent -221,-124 189,123, body extent -156,-116 157,116, height 91
SOD-123 [mm] "On Semi recommended land pattern"
  rect 0.915x1.22 smd: 1(-1.637,0) 2(1.637,0)
  silkscreen extent -2.74,-1.17 2.03,1.17, body extent -1.93,-0.9 1.93,0.9, height 1.35
sod-323 [mm] "NXP recommended land pattern"
  rect 0.6x0.6 smd paste-0.05: 1(-1.1,0) 2(1.1,0)
  silkscreen extent -2.06,-0.86 1.52,0.86, body extent -1.3,-0.67 1.3,0.68, height 1.1
SOD-523 [mm] "NXP Semiconductor recommended land pattern, nominal STEP model"
  rect 0.8x0.6 smd paste-0.05: 1(-0.55,0) 2(0.55,0)
  silkscreen extent -1.6,-0.63 1.2,0.64, body extent -0.8,-0.4 0.8,0.4, height 0.72
SOT-23 [mm] "SOT23, 3-Leads, Body 2.9x1.3mm, Pitch 0.95mm, Lead Span 2.5mm, IPC Medium Density"
  rrect50% 1x0.6 smd: 1(-1.2,0.95) 2(-1.2,-0.95) 3(1.2,0)
  silkscreen extent -1.63,-1.5 0.7,1.5, body extent -1.16,-1.45 1.21,1.45, height 1
SOT-323 [mm] "Zetex recommended land pattern.  March 2007"
  rect 0.8x0.6 smd: 1(-0.8,0.65) 2(-0.8,-0.65) 3(0.8,0)
  silkscreen extent -1.14,-1.22 0.77,1.22, body extent -1.13,-1.13 1.12,1.12, height 1.13
THERM_B57236S0 [mm] "EPCOS"
  round 1.35 hole 0.85: 1(-2.5,0) 2(2.5,0)
  silkscreen extent -5.75,-3 5.75,3, body extent -5.75,-3 5.7,3, height 15.99
TI_STACKED_OVERLAY_SMALL [mil]
  silkscreen extent -418,-98 418,98
TO-220_FullPAK_Offset [mil] "Infineon  PG-TO220-3-31"
  rect 76x118.11 hole 50: 1(-100,0)
  oval 76x118.11 hole 50: 2(0,-100) 3(100,0)
  silkscreen extent -190,-75 190,115, body extent -190,-112 190,115, height 902
TO-220AB [mil] "Copied from Altium's version of TO3B"
  rrect25% 76x118.11 hole 50: 1(-100,0)
  oval 76x118.11 hole 50: 2(0,0) 3(100,0)
  silkscreen extent -221,-59 221,126, body extent -221,-59 221,126, height 765
TRANS_NexFET_Q5A [mm] "TI recommended land pattern (nominal) M0139-01"
  rect 0.75x0.675 smd paste-0.1: 1(-2.776,1.917) 2(-2.776,0.639) 3(-2.776,-0.639) 4(-2.776,-1.917)
  rect 0.655x0.675 smd paste-0.1: 5(2.776,-1.917) 6(2.776,-0.639) 7(2.776,0.639) 8(2.776,1.917)
  rect 4.295x4.51 smd paste-2.2: 9(0.301,0)
  silkscreen extent -3.4,-2.8 3.4,2.8, body extent -3.05,-2.5 3.05,2.5, height 1.11
tsop-6 [mm] "TSOP, 6-Leads, Body 3.1x1.7mm (max), Pitch 0.95mm, IPC Medium Density"
  rrect50% 1.4x0.55 smd: 1(-1.2,0.95) 2(-1.2,0) 3(-1.2,-0.95) 4(1.2,-0.95) 5(1.2,0) 6(1.2,0.95)
  silkscreen extent -2.31,1.68 -2.06,1.93, body extent -0.85,-1.55 0.85,1.55, height 1.1
VAR_S10K275E2 [mm] "EPCOS"
  round 1.6 hole 1.1: 1(-3.75,1.1) 2(3.75,-1.1)
  silkscreen extent -6,-2.7 6,2.7, body extent -5.98,-2.7 5.98,2.7, height 14.99
WE_75034300X [mm] "TRANS OR IND, PITCH 5MM, 29.84X24X33MM, TH-10PIN"
  rect 1.75x1.75 / inner round 1.75 / far side rect 1.75x1.75 hole 1.25: 1(-10,-8.7)
  round 1.75 hole 1.25: 2(-5,-8.7) 3(0,-8.7) 4(5,-8.7) 5(10,-8.7) 6(10,8.7) 7(5,8.7) 8(0,8.7) 9(-5,8.7) 10(-10,8.7)
  silkscreen extent -14.92,-13 14.92,12, body extent -14.65,-12.09 15.19,11.91, height 33
XFMR_CTX16-17298 [mil]
  round 90 hole 52: 2(415.78,138.59) 4(-346.48,69.3) 6(-485.08,69.3) 8(-415.78,-138.59) 11(415.78,-138.59)
ZLJ_500x1100 [mm] "TH, 2-Leads, Dia 5mm,  Lead Spacing 2mm"
  rect 1.25x1.25 hole 0.75: 1(-1,0)
  round 1.25 hole 0.75: 2(1,0)
  silkscreen extent -2.75,-2.75 2.75,2.75, body extent -2.73,-2.75 2.75,2.75, height 12.51

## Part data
BR1: library part GBU4A-BP, "RECT BRIDGE GPP 6A 600V GBU"
C1: "CAP, Film, 0.68 µF, 630 V, +/- 20%, TH"
C2: library part EEUED2E820S, "CAP ALUM 82UF 20% 450V RADIAL"
C3 C4: "CAP, Film, 0.33 µF, 630 V, +/- 20%, TH"
C5 C6: library part DE6E3KJ222MN3A, "CAP CER 1500PF 300VAC 20% RADIAL"
C7 C8 C35: library part DE6E3KJ222MN3A, "CAP CER 2200PF 300VAC 20% RADIAL"
C9 C34: "CAP, CERM, 1 µF, 50 V, +/- 10%, X5R, 0603"
C10: "CAP, CERM, 18 pF, 50 V, +/- 5%, C0G/NP0, 0603"
C11 C13 C15 C23: "CAP, CERM, 1000 pF, 50 V, +/- 5%, C0G/NP0, 0603"
C12: "CAP, CERM, 1 µF, 16 V, +/- 10%, X5R, 0603"
C14: "CAP, CERM, 3.3 µF, 25 V, +/- 10%, X5R, 0603"
C16: "CAP, CERM, 10 µF, 25 V, +/- 10%, X5R, 0805"
C17: "CAP, Film, 0.1 µF, 305 V, +/- 20%, TH"
C18: "CAP, CERM, 2200 pF, 630 V, +/- 10%, X7R, 1206"
C19: "CAP, AL, 47 µF, 35 V, +/- 20%, 0.4 ohm, TH"
C20: library part EEU-FC1H100, "CAP ALUM 10UF 20% 50V RADIAL"
C21 C41: "CAP, CERM, 0.1 µF, 50 V, +/- 10%, X7R, 0603"
C22: "CAP, CERM, 4.7 pF, 50 V, +/- 5%, C0G/NP0, 0603"
C24: "CAP, CERM, 680 pF, 50 V, +/- 10%, X7R, 0603"
C25: "CAP, CERM, 10 pF, 50 V, +/- 5%, C0G/NP0, 0603"
C26: "CAP, CERM, 2.2 pF, 50 V, +/- 11%, C0G/NP0, 0603"
C27: "CAP, CERM, 47 pF, 50 V, +/- 5%, C0G/NP0, 0603"
C28: "CAP, CERM, 0.01 µF, 250 V, +/- 10%, X7R, 0805"
C29 C30: library part EKY-160ELL102MK15S, "CAP, AL, 1200 µF, 35 V, +/- 20%, 0.024 ohm, TH"
C31: library part EKY-160ELL152MJ30S, "CAP ALUM 680UF 20% 35V RADIAL"
C32: "CAP, CERM, 1 µF, 50 V, +/- 10%, X7R, 1206"
C33: "CAP, CERM, 0.1 µF, 50 V, +/- 5%, X7R, 1206"
C36: "CAP, CERM, 5.6 pF, 50 V, +/- 5%, C0G/NP0, 0603"
C37: "CAP, CERM, 0.47 µF, 50 V, +/- 10%, X7R, 0805"
C38: "CAP, CERM, 0.047 µF, 50 V, +/- 10%, X7R, 0603"
C39 C40: library part VY2102M29Y5UG63V7, "CAP CER 4700PF 440VAC Y5U RADIAL"
C42: "CAP, CERM, 0.1 µF, 16 V, +/- 10%, X5R, 0603"
C43: "CAP, CERM, 0.22 µF, 16 V, +/- 10%, X7R, 0603"
D1: "Diode, Ultrafast, 600 V, 3 A, SMC"
D2: library part RS3K-E3/9AT, "DIODE GEN PURP 600V 3A SMC"
D3: "Diode, Switching, 100 V, 0.2 A, SOD-323"
D4 D5: "Diode, P-N, 1000 V, 1 A, 3.9x1.7x1.8mm"
D6: library part HLMP1523, "LED SS HI EFF GREEN DIFF 3MM"
D7: library part SMCJ100A, "Diode, TVS, Uni, 130V, 1500 W, TH"
D8: library part RS3K-E3/9AT, "Diode, Switching, 1000 V, 3 A, SMC"
D9: "Diode, Switching, 200 V, 0.4 A, SOT-23"
D11: "Diode, Zener, 24V, 500mW, SOD-123"
D12: "Diode, Zener, 4.7 V, 300 mW, SOD-523"
F1: "Fuse, 2 A, 250 V, TH"
FID1 FID2 FID3: "Fiducial mark.  There is nothing to buy or mount."
H1 H2 H3 H4: "MACHINE SCREW PAN PHILLIPS 4-40"
HS1 HS2: "HEATSINK TWISTED FIN TO-220 Vertical"
HS3: library part 593002B00000G, "HEATSINK TO-220 19.05X13.21MM"
J1: "TERM BLOCK 3POS 5.08MM, TH"
J2: "Terminal Block, 5.08mm, 4x1, TH"
L1: library part XFMR_CTX16-17298, "PFC choke with primary side sensing winding"
L2 L4: library part 744823210, "Coupled inductor, 7mH, 2 A, 0.045 ohm, 3.7-7.1 mH"
L3: library part 744823210, "Coupled inductor, 20 mH, 1.5A, 0.270 ohm, +/- 30%, TH"
L5: library part PM2110-1R0M-RC, "Inductor, Toroid, 220µH, 2.4 A, 0.120 ohm, TH"
LBL1: library part THT-14-423-10, "Thermal Transfer Printable Labels, 0.650\" W x 0.200\" H - 10,000 per roll"
Logo1: library part TI_Logo, "Texas Instrument Corporate Signature"
Logo2: library part Pb-Free
Logo3: library part FCC_disclaimer, "FCC_disclaimer"
Q1: library part IPP60R190P6, "MOSFET N-CH 600V 10.6A TO220"
Q2: library part IPP50R199CP, "MOSFET N-CH 650V 15A TO220F"
Q3: library part IRFB4410ZPBF, "MOSFET N-CH 200V 26A TO-220FP"
Q4: "MOSFET, N-CH, 40 V, 15 A, SON 5x6mm"
Q5: library part "MMBT2222A, Fairchild Semiconductor", "Transistor, NPN, 40 V, 0.15 A, SOT-23"
Q6: library part "CMST2222A TR, Central Semiconductor", "Transistor, NPN, 40 V, 0.6 A, SOT-323"
Q7 Q8: library part "MMBT2907A, Fairchild Semiconductor", "Transistor, PNP, 40 V, 0.6 A, SOT-323"
R1: "RES, 0.3, 1%, 1 W, 2010"
R2: "RES, 2.7, 5%, 0.75 W, 2010"
R3 R4 R59: "RES, 680 k, 1%, 0.25 W, 1206"
R5: "RES, 8.25 k, 1%, 0.125 W, 0805"
R6 R7 R8: "RES, 340 k, 1%, 0.25 W, 1206"
R9: "RES, 10.5 k, 1%, 0.1 W, 0603"
R10: "RES, 5.11 k, 1%, 0.1 W, 0603"
R11: "RES, 332, 1%, 0.1 W, 0603"
R12: "RES, 22.1 k, 1%, 0.1 W, 0603"
R13 R33 R47 R57: "RES, 100 k, 1%, 0.1 W, 0603"
R14: "RES, 10.0, 1%, 0.125 W, 0805"
R15: "RES, 1.1, 5%, 0.125 W, 0805"
R16 R25 R39 R40 R52: "RES, 10.0 k, 1%, 0.1 W, 0603"
R17 R18: "RES, 301 k, 1%, 0.25 W, 1206"
R19: "RES, 5.10 k, 1%, 0.25 W, 1206"
R20: "RES, 6.81 k, 1%, 0.125 W, 0805"
R21: "RES, 14.7 k, 1%, 0.1 W, 0603"
R22 R23 R24: "RES, 221 k, 1%, 0.25 W, 1206"
R26: library part CSRN2010FKR750, "RES SMD 1.47 OHM 1% 3/4W 2010"
R27: library part CSRN2010FKR200, "RES SMD 0.18 OHM 1% 1/2W 2010"
R28: "RES, 5.1, 5%, 0.1 W, 0603"
R29 R55: "RES, 1.21 k, 1%, 0.1 W, 0603"
R30: "RES, 47.5, 1%, 0.125 W, 0805"
R31: "RES, 71.5 k, 1%, 0.1 W, 0603"
R32: "RES, 19.6 k, 1%, 0.1 W, 0603"
R34: "RES, 20.5 k, 1%, 0.1 W, 0603"
R35: "RES, 13.7 k, 1%, 0.1 W, 0603"
R36: "RES, 0, 5%, 0.1 W, 0603"
R37: "RES, 402, 1%, 0.1 W, 0603"
R38 R42: "RES, 750 k, 1%, 0.1 W, 0603"
R41: "RES, 47.5 k, 1%, 0.1 W, 0603"
R43: "RES, 20.0 k, 1%, 0.1 W, 0603"
R44: "RES, 1.50, 1%, 0.1 W, 0603"
R45: "RES, 100, 1%, 0.25 W, 1206"
R46: "RES, 47.5, 1%, 0.1 W, 0603"
R48: "RES, 44.2 k, 1%, 0.1 W, 0603"
R49: "RES, 1.00 k, 1%, 0.1 W, 0603"
R50: "RES, 1.50 k, 1%, 0.1 W, 0603"
R51: "RES, 4.99 k, 1%, 0.1 W, 0603"
R53: "RES, 100 k, 1%, 0.25 W, 1206"
R54: "RES, 470 k, 1%, 0.1 W, 0603"
R56: "RES, 332 k, 1%, 0.1 W, 0603"
R58: library part 3266W-1-203LF, "TRIMMER 100K OHM 0.5W TH"
R60: "RES, 493 k, 0.1%, 0.1 W, 0603"
RCL1: library part B57236S0100M000, "ICL 4.7 OHM 20% 4.6A 11.51MM"
RV1: "Varistor 275V RMS 10MM Radial, TH"
T1: "TRANSFORMER, 160.0uH, 10%, TH-10PIN"
TP1 TP2 TP3 TP8: "Test Point, Miniature, Red, TH"
TP4 TP5 TP6 TP7 TP9: "Test Point, Miniature, Black, TH"
U1: "TRANSITION MODE PFC CONTROLLER, D0008A"
U2: "Constant-Voltage, Constant-Current Flyback Controller Using Opto-Coupler Feedback, D0007A"
U3: library part UCC24630DBV, "SYNCRONOUS RECTIFIER CONTROLLER WITH LOW POWER STANDBY, DBV0006A"
U4 U8: "PRECISION PROGRAMMABLE REFERENCE, DBZ0003A"
U5: "HIGH SIDE OR-ING FET CONTROLLER"
U6: "Optocoupler, 5 kV, 50-600% CTR, TH-4"
U7: library part TMP300BIDCK, "1.8V, Resistor-Programmable TEMPERATURE SWITCH and ANALOG OUT TEMPERATURE SENSOR, DCK0006A"
XF1: "FUSE HOLDER RADIAL 250V 6.3A PCB"
ZZ1: library part AssemblyNoteLabel
ZZ2 ZZ3 ZZ4: library part AssemblyNote

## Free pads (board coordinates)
  round 90 hole 52: 0(200,808) 12(900,808)
  oval 450x20 hole 20 slot 450 at 0 deg unplated mask+5: 0(2009,2706)
  oval 20x100 hole 20 slot 100 at 90 deg unplated mask+5: 0(2899,2821) 0(2907,2638) 0(3305,2822) 0(3314,2637) 0(4065,2101)
  oval 425x20 hole 20 slot 425 at 0 deg unplated mask+5: 0(3102,2781) 0(3110,2678)
  oval 200x20 hole 20 slot 200 at 0 deg unplated mask+5: 0(4157,2141)
  oval 20x200 hole 20 slot 200 at 90 deg unplated mask+5: 0(4379,2117)
  oval 300x20 hole 20 slot 300 at 0 deg unplated mask+5: 0(4521,2026)

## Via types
v1: diameter 24, hole 12, Top Layer to Bottom Layer, 92 vias

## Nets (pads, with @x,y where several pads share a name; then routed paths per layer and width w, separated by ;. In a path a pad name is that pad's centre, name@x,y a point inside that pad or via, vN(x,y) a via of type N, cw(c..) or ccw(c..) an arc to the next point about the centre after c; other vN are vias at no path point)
GND: C1.2 C2.2 C9.2 C10.2 C11.2 C12.2 C13.2 C14.2 C15.2 C16.2 C17.2 C19.2 C20.2 C21.2 C22.2 C36.2 C41.2 C43.2 HS1.1 HS2.1 L1.11 L5.2 pad.12 Q7.3 R1.1 R2.1 R5.1 R9.1 R16.2 R20.2 R21.2 R26.1 R27.1 R32.1 R34.1 R54.1 R60.1 T1.4 TP4.1 TP5.1 TP7.1 U1.6 U2.4 U7.1 U7.2 U8.3 | length 1521.3
  Bottom Layer w15: R16.2@1171,992.5 1171,1255 1225.55,1309.55 R1.1@1344,1309.55 ; v1(1723,836) 1723.5,835.5 R9.1@1723.5,789 ; v1(1752,881.5) C10.2@1787,846.49 ; Q7.3@1970.5,1017 2006,1017 v1(2007,1016) ; v1(2074.5,1111.5) 2075,1111 C41.2@2116.5,1111 ; v1(2188,1482) 2188,1481 2221.57,1447.43 U8.3@2242,1447.43
  Bottom Layer w20: C16.2@1220.22,313.72 1220.22,357.22 1221,358 v1(1221,360) ; v1(1258,480) 1258.27,480.27 C14.2@1300.5,480.27 ; v1(1315,362) 1315,360 1315.22,359.78 R20.2@1315.22,315.72 ; v1(1381,450) 1381.46,450.46 C12.2@1381.46,491.13 ; v1(1419,170) 1419.5,170.5 R21.2@1419.5,213 ; R5.1@1424,708 1426.5,705.5 C15.2@1502,705.5 1502,739 v1(1502,747) ; v1(1524,407) 1524,410 C13.2@1524,448.5 ; C11.2@1595,850.5 v1(1595,898) ; U1.6@1782.71,666.72 1844.72,666.72 1845,667 v1(1848,667) ; v1(1793.54,387.37) 1794,387.83 C9.2@1794,428.5 ; v1(1950,785) C36.2@1950,827.5 ; v1(1982,702) U2.4@2015.05,702 ; v1(2002,486) 2002,492 R34.1@2002,527.16 ; v1(2067,485) 2067,488 C22.2@2067,526.5 ; v1(2131.95,488.13) 2131.95,494.13 R54.1@2131.94,529.29 ; v1(2194.95,488.13) 2194.95,494.13 R32.1@2194.94,529.29 ; C21.2@2234,751.5 2234,788 v1(2234,793)
  other v1: 1319,1454 1353,1454 1388,1454 1961,1824 2000,1824 1920,1825
GND-2: C26.2 C27.1 C29.2 C30.2 C37.1 D11.2 HS3.1 L4.3 Q3.3 R39.1 R40.2 R41.2 R43.2 R45.2 R48.2 R53.1 U3.5 U4.3 | length 434.4
  Bottom Layer w20: v1(3245.5,226.57) U4.3@3287,226.57 ; v1(3341.5,228.5) R48.2@3383,228.5 ; v1(3491,360) R41.2@3491,407.5 ; v1(3516.5,611.5) R40.2@3564,611.5 ; v1(3556,360) C27.1@3556,407.5 ; C26.2@3696.5,413 v1(3744,413) ; R39.1@3697.5,349 v1(3745,349) ; U3.5@3720.24,510 v1@3773,510 ; v1(3770,507) v1@3773,510 ; C37.1@3829,512 3775,512 v1@3773,510
GND-3: C31.2 C32.2 C33.2 C34.2 C40.1 D12.2 J2.1 J2.2 L4.1 R55.1 TP9.1 U5.2 U5.3 | length 1474.5
  Top Layer w30: L4.1@4103.96,1565.04 4160.04,1565.04 4197,1602 4197,2033.36 C40.1@4144.36,2086
  Bottom Layer w20: v1(4143,468) R55.1@4143,525.5
  Bottom Layer w30: D12.2@4557,1219.35 4557,1073 4604,1026 4604,609 ; TP9.1@4569,144 4569,317
GNDE: C5.2 C6.2 C7.2 C8.2 C39.2 C40.2 J1.1 | length 2283
  Top Layer w40: C8.2@2790,2673.64 C7.2@2790,2770.36 ; C6.2@3410,2677.64 C5.2@3410,2783.36
  Bottom Layer w40: C7.2@2790,2770.36 2838.64,2770.36 2879,2730 3357.64,2730 C6.2@3410,2677.64 3624,2463.64 3624,2270 3689,2205 3973,2205 4067,2299 J1.1@4484,2299
NetBR1_1: BR1.1 C4.1 RCL1.2
NetBR1_2: BR1.2 D4.2 L3.3 | length 178.7
  Bottom Layer w30: D4.2@1711.67,2740.06 1782.61,2811 BR1.2@1861,2811
NetBR1_3: BR1.3 D5.2 L3.2 | length 160.3
  Bottom Layer w30: D5.2@1709.67,2632.65 1768.35,2632.65 1790,2611 BR1.3@1861,2611
NetBR1_4: BR1.4 C4.2 L5.1
NetC1_1: C1.1 D2.2 L1.6 RCL1.1 TP6.1 | length 454.7
  Bottom Layer w30: TP6.1@379,3116 473.57,3116 RCL1.1@579.57,3010
  Bottom Layer w80: L1.6@306,1592.01 451.51,1737.51 D2.2@451.51,1742
NetC2_1: C2.1 C17.1 C18.1 C35.1 D1.1 D2.1 D7.2 R6.1 T1.1 U2.8 | length 3187.1
  Top Layer w80: C2.1@1400,1904.05 1400,2036 1536,2172 2217.85,2172 C17.1@2408.85,1981
  Bottom Layer w20: U2.8@2165.07,891 2206,891 2316.5,1001.5 2316.5,1089.5 2545,1318 2545,1394 2607.48,1456.48 T1.1@2607.48,1538.7
  Bottom Layer w40: C2.1@1400,1904.05 1401.97,1902.09 R6.1@1500,1902.09 ; v1(2625,2043) 2635,2053 C35.1@2841.36,2053
  Bottom Layer w80: D2.1@732.49,1742 822.51,1742 858,1777.49 D1.1@959,1777.49 1202.49,1777.49 1329.05,1904.05 C2.1@1400,1904.05
  other v1: 2465,2043 2505,2043 2545,2043 2585,2043 2448.97,2083 2485,2083 2525,2083 2565,2083 2605,2083
NetC3_1: C3.1 C5.1 F1.1 L2.4 R22.1 RV1.2 TP1.1 XF1.1 | length 283.9
  Bottom Layer w40: TP1.1@3147,3129 3197.36,3078.64 C5.1@3410,3078.64
NetC3_2: C3.2 C6.1 J1.2 L2.1 R24.2 RV1.1 TP2.1 | length 408.8
  Top Layer w40: L2.1@3179.74,2594.2 3211.8,2594.2
  Bottom Layer w40: TP2.1@3182,2330 3234.36,2382.36 C6.1@3410,2382.36 ; R24.2@3826,2551.91 3826,2508 3845,2489 C3.2@3845,2432.72
NetC7_1: C7.1 L2.3 L3.4
NetC8_1: C8.1 L2.2 L3.1
NetC10_1: C10.1 R12.1 U1.5 | length 380.1
  Bottom Layer w15: R12.1@1723,491.5 1723,534.29 1689,568.29 1689,680 1725.72,716.72 U1.5@1782.71,716.72 1787,721.01 C10.1@1787,783.5
NetC11_1: C11.1 R11.1 U1.4 | length 150.6
  Bottom Layer w20: R11.1@1514,789.5 1590.47,789.5 1593.74,786.24 U1.4@1593.74,716.72
NetC12_1: C12.1 R10.2 U1.2 | length 253.9
  Bottom Layer w20: C12.1@1444.45,491.13 1444.45,520.55 1434,531 R10.2@1434,555.76 1487.76,555.76 1548.72,616.72 U1.2@1593.74,616.72
NetC13_1: C13.1 Q5.3 R8.1 R9.2 U1.1 | length 1585.2
  Top Layer w20: v1(1571,1538) 1573,1540 1611,1540 1750,1401 v1(1750,1349)
  Bottom Layer w20: R8.1@1500,1555.91 1553.09,1555.91 v1(1571,1538) ; Q5.3@1507.24,322 1507.24,357.76 1482.14,382.86 1482.14,491 1502.63,511.5 C13.1@1524,511.5 1559.5,511.5 1593.74,545.74 U1.1@1593.74,566.72 1647.72,566.72 1663.5,582.5 1663.5,786 R9.2@1660.5,789 1660.5,1153.5 1752,1245 1752,1347 v1(1750,1349)
NetC14_1: C14.1 R10.1 | length 75.7
  Bottom Layer w20: C14.1@1300.5,543.26 1325.2,543.26 1337.7,555.76 R10.1@1371.01,555.76
NetC15_1: C15.1 R5.2 R59.2 U1.3 | length 4116.2
  Bottom Layer w20: R59.2@1037.91,2526 1036.91,2525 142.6,2525 105,2487.4 105,1144.6 417,832.6 417,701.57 525.57,593 1389,593 R5.2@1424,628 1462.8,628 1477.3,642.5 C15.1@1502,642.5 1522.5,642.5 1546.72,666.72 U1.3@1593.74,666.72
NetC16_1: C16.1 Q5.1 R19.1 R20.1 | length 434.3
  Bottom Layer w20: R19.1@1118.22,232.63 1119.31,233.72 C16.1@1220.22,233.72 ; 1185.22,232.63 C16.1@1219.14,232.63 ; R20.1@1286.14,232.63 C16.1@1219.14,232.63 ; Q5.1@1412.76,284.6 1384.6,284.6 1375,275 1375,248 1362.72,235.72 R20.1@1315.22,235.72 1313.22,233.72 C16.1@1220.22,233.72 ; C16.1@1219.14,232.63 C16.1@1220.22,233.72
NetC18_2: C18.2 D7.1 D8.1
NetC22_1: C22.1 R31.1 R32.2 R54.2 U2.2 | length 310.4
  Bottom Layer w20: C22.1@2067,589.5 2129.16,589.5 R54.2@2131.94,592.28 ; U2.2@2115.07,702.02 2115.07,659.93 2131.94,643.06 R54.2@2131.94,592.28 ; R31.1@2259,593.5 2257.78,592.28 R32.2@2194.94,592.28 R54.2@2131.94,592.28
NetC23_1: C23.1 C24.1 R49.1 U4.1 U6.2 | length 305.5
  Bottom Layer w20: U6.2@3057,458 3099.5,458 R49.1@3124,433.5 3186.07,433.5 C23.1@3188,435.42 3188,370.5 C24.1@3189.5,369 3189.5,368.15 3249.6,308.06 U4.1@3249.6,297.43
NetC23_2: C23.2 R51.2 | length 70.9
  Bottom Layer w20: C23.2@3250.99,435.42 3318.93,435.42 R51.2@3321,437.5
NetC24_2: C24.2 R48.1 R51.1 R57.1 R58.3 U4.2 | length 443.4
  Bottom Layer w20: C24.2@3252.5,369 3315.5,369 R51.1@3321,374.5 3321,344 3324.4,340.6 U4.2@3324.4,297.43 3330.34,291.5 R48.1@3383,291.5 3391.5,291.5 3404.5,278.5 R57.1@3445,278.5 3449.2,274.3 3522,274.3 3536.3,260 R58.3@3595.06,260 ; R58.3@3593.06,262 R58.3@3601,262
NetC25_1: C25.1 R46.2 R50.1 R56.2 | length 205.2
  Bottom Layer w20: C25.1@3186.07,303 R50.1@3186.07,238 3186.07,161.43 R56.2@3186.5,161 R46.2@3186.51,98
NetC25_2: C25.2 R49.2 R50.2 U6.1 | length 205.1
  Bottom Layer w20: U6.1@3057,358 3086.73,358 3099.24,370.5 R49.2@3124,370.5 3124,303.92 C25.2@3123.08,303 R50.2@3123.08,238
NetC26_1: C26.1 R38.1 R39.2 U3.1 | length 317.6
  Bottom Layer w20: R39.2@3634.5,349 3633.5,350 C26.1@3633.5,413 3633.5,437.7 3625.76,445.44 U3.1@3625.76,472.6 3653.6,472.6 3665.41,484.41 3665.41,568.18 3684,586.77 R38.1@3684,622.5
NetC27_2: C27.2 R41.1 R42.2 U3.2 | length 217.5
  Bottom Layer w20: R42.2@3425,471.5 3490,471.5 R41.1@3491,470.5 C27.2@3556,470.5 3595.5,510 U3.2@3625.76,510
NetC28_1: C28.1 R45.1 | length 93.3
  Bottom Layer w20: C28.1@3542,1096 3633.91,1096 R45.1@3634.91,1097
NetC28_2: C28.2 Q3.2 R38.2 T1.6 T1.7 | length 410.9
  Bottom Layer w30: T1.7@3292.52,948.15 3292.52,1022.52 3366,1096 C28.2@3462,1096 ; R38.2@3684,685.5 3684,714 3718,748 Q3.2@3718,808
